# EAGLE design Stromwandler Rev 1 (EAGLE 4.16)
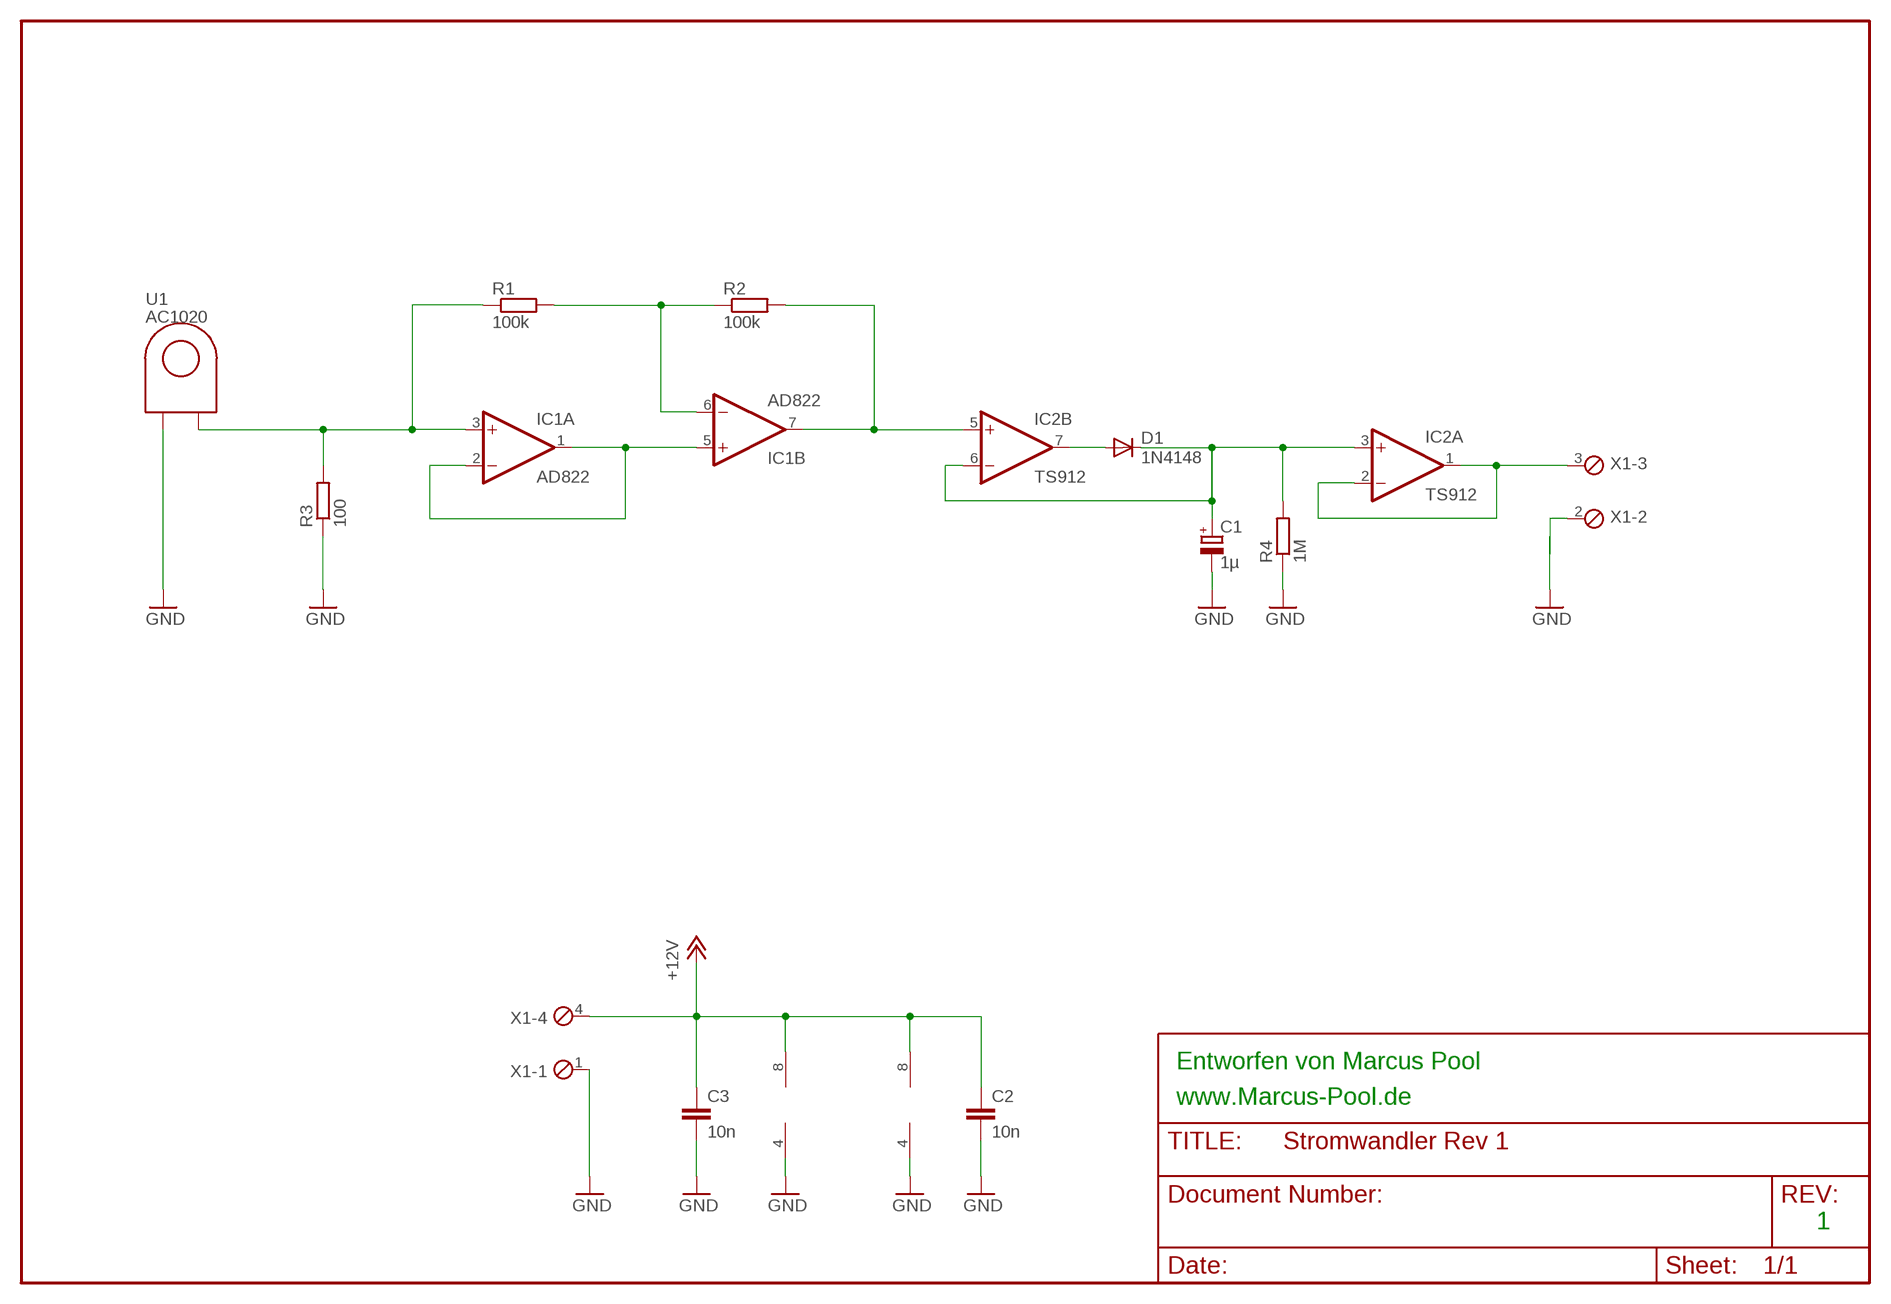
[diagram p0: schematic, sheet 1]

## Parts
C1  1µ  CPOL-EUE2.5-5  [E2,5-5]
C2  10n  C-EU050-025X075  [C050-025X075]
C3  10n  C-EU050-025X075  [C050-025X075]
D1  1N4148  DIODE-D-7.5  [D-7.5]
IC1  AD822  LM1458N  [DIL08]
IC2  TS912  LM358N  [DIL08]
R1  100k  R-EU_0204/7  [0204/7]
R2  100k  R-EU_0204/7  [0204/7]
R3  100  R-EU_0204/7  [0204/7]
R4  1M  R-EU_0204/7  [0204/7]
U1  AC1020  AC10XX  [AC10XX]
X1  MPT4  [4POL254]

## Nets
+12V: C2.1 C3.1 IC1.8(P:V+) IC2.8(P:V+) X1.4
GND: C1.- C2.2 C3.2 IC1.4(P:V-) IC2.4(P:V-) R3.1 R4.1 U1.P$3 X1.1 X1.2
N$1: IC1.3(A:+IN) R1.1 R3.2 U1.P$2
N$2: C1.+ D1.C IC2.3(A:+IN) IC2.6(B:-IN) R4.2
N$3: IC1.6(B:-IN) R1.2 R2.1
N$4: IC1.1(A:OUT) IC1.2(A:-IN) IC1.5(B:+IN)
N$6: IC1.7(B:OUT) IC2.5(B:+IN) R2.2
N$7: IC2.1(A:OUT) IC2.2(A:-IN) X1.3
N$8: D1.A IC2.7(B:OUT)

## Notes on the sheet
- Entworfen von Marcus Pool
- www.Marcus-Pool.de
- 1

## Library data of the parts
C1 = rcl:CPOL-EU: POLARIZED CAPACITOR, European symbol
C2 C3 = rcl:C-EU: CAPACITOR, European symbol
D1 = diode:DIODE-: DIODE
IC1 = linear:*1458: OP AMP
IC2 = linear:LM358: OP AMP also LM158; LM258; LM2904 Source: http://cache.national.com/ds/LM/LM158.pdf
R1-R4 = rcl:R-EU_: RESISTOR, European symbol
U1 = AC10xx:AC10XX
X1 = con-phoenix-254:MPT4: PHOENIX CONNECTOR

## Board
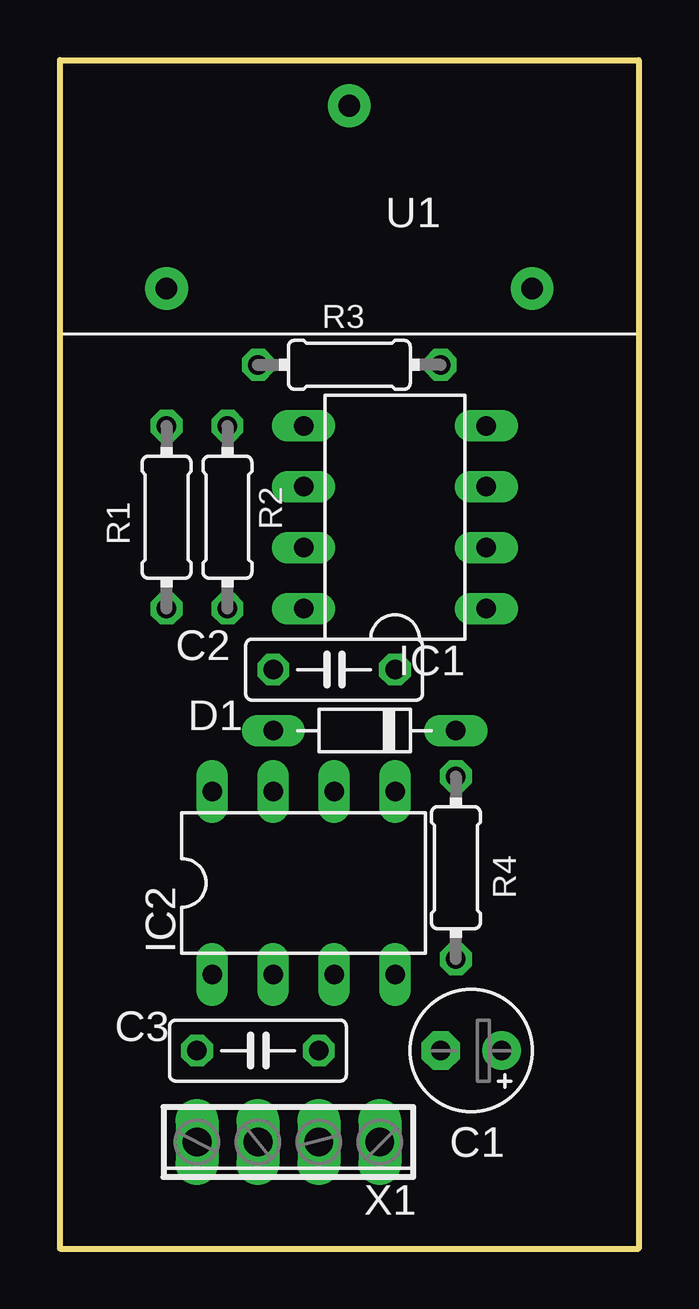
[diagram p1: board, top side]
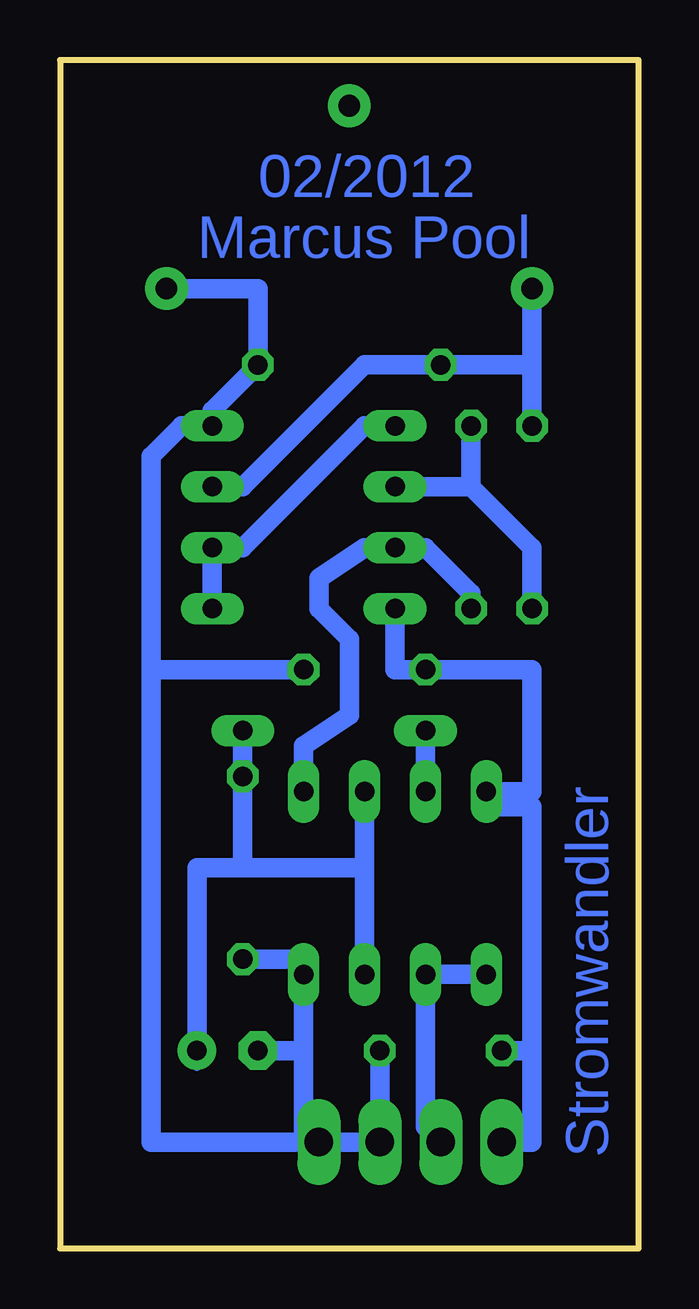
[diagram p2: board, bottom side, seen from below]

Size 24.13 x 49.53 mm. Coordinates in mm from the lower left corner, seen from the top.
Outline: 0,0 0,49.53 24.13,49.53 24.13,0 0,0
Copper layers (1+16): Top 0.035mm / dielectric 1.5mm / Bottom 0.035mm
Design rules "default": minimum track width 10mil, minimum drill 24mil, track to track 8mil, track to pad 8mil, pad to pad 8mil, via to via 8mil, smd to smd 8mil, copper to edge 40mil, drill to drill 8mil, minimum pad ring 10mil, minimum via ring 8mil, stop-mask expansion 4mil, vias tented up to drill 0mil, thermal gap 10mil

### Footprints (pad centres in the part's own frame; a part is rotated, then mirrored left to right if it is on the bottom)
E2,5-5 = drill 0.813 pad 1.6 round: + -1.27,0 | drill 0.813 pad 1.6 octagon: - 1.27,0
C050-025X075 = drill 0.813 octagon: 1 -2.54,0; 2 2.54,0
D-7.5 = drill 0.813 long: A 3.81,0; C -3.81,0
DIL08 = drill 0.813 long: 1 -3.81,-3.81; 2 -1.27,-3.81; 3 1.27,-3.81; 4 3.81,-3.81; 5 3.81,3.81; 6 1.27,3.81; 7 -1.27,3.81; 8 -3.81,3.81
0204/7 = drill 0.813 octagon: 1 -3.81,0; 2 3.81,0
AC10XX = drill 0.9 pad 1.778 round: P$1 0,-3.81; P$2 7.62,3.81; P$3 -7.62,3.81
4POL254 = drill 1.2 long: 1 -3.81,0; 2 -1.27,0; 3 1.27,0; 4 3.81,0

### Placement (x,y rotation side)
C1  17.14,8.26 180 top
C2  11.43,24.13 0 top
C3  8.25,8.26 0 top
D1  12.7,21.59 180 top
IC1  13.97,30.48 90 top
IC2  10.16,15.24 0 top
R1  4.45,30.48 270 top
R2  6.99,30.48 270 top
R3  12.07,36.83 180 top
R4  16.51,15.88 90 top
U1  12.07,43.81 180 top
X1  9.53,4.45 180 top

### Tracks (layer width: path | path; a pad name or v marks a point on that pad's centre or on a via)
+12V
  Bottom 0.813: 8.25,24.13 10.16,24.13 IC1.8 | 8.25,24.13 4.45,24.13 4.45,19.05 IC2.8 6.35,18.41 4.45,18.41 | 4.45,18.41 4.45,8.26 C3.1 | 8.25,24.13 C2.1 | 4.45,18.41 4.45,4.45 X1.4
GND
  Bottom 0.813: U1.P$3 15.88,40.01 R3.1 17.78,34.92 IC1.4 19.05,34.29 20.32,33.02 20.32,24.13 | 20.32,24.13 C2.2 | 20.32,24.13 20.32,4.45 13.97,4.45 | 13.97,4.45 13.97,8.26 | 13.97,8.26 IC2.4 13.97,12.06 R4.1 | 13.97,4.45 X1.1 X1.2 C3.2 | 13.97,8.26 C1.-
N$1
  Bottom 0.813: 4.45,36.83 U1.P$2 | R3.2 8.89,36.83 | R1.1 4.45,36.83 | 4.45,36.83 R3.2 | IC1.3 16.51,31.75 11.43,36.83 R3.2
N$2
  Bottom 0.406: 18.41,7.62 C1.+
  Bottom 0.813: IC2.3 11.43,15.88 | 11.43,15.88 IC2.6 | 11.43,15.88 16.51,15.88 | 16.51,15.88 R4.2 D1.C | 18.41,10.16 18.41,15.88 16.51,15.88 | 18.41,10.16 18.41,9.53 | 18.41,10.16 C1.+
N$3
  Bottom 0.813: 6.99,31.75 IC1.6 | R1.2 4.45,29.21 6.99,31.75 | 6.99,31.75 R2.1
N$4
  Bottom 0.813: IC1.1 IC1.2 16.51,29.21 11.43,34.29 IC1.5
N$6
  Bottom 0.813: R2.2 6.99,27.3 8.89,29.21 IC1.7 11.43,29.21 13.34,27.94 13.34,26.67 12.07,25.4 12.07,22.23 13.97,20.95 IC2.5
N$7
  Bottom 0.813: IC2.1 IC2.2 8.89,5.08 X1.3
N$8
  Bottom 0.813: IC2.7 D1.A

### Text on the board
Bottom: 02/2012 | Marcus Pool | Stromwandler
